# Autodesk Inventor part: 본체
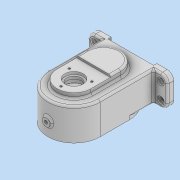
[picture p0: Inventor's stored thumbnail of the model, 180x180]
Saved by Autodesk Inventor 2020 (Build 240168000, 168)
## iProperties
Created: 2021-05
Part Number: 본체
Material: 일반
Document SubType Name: Modeling
Designer: Owner
Density: 1 g/cm^3
Appearance: 기본값
Mass: 280.11 g
Surface Area: 582.454 cm^2
Volume: 280.11 cm^3
Author: Owner
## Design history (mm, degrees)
sketch "스케치2"
  geometry: L1 (-61, 21.643)-(-35, 21.643); L2 (-35, 21.643)-(-35, -24.357); L3 (-35, -24.357)-(-61, -24.357); L4 (-61, -24.357)-(-61, 21.643); L5 (35, 21.643)-(61, 21.643); L6 (61, 21.643)-(61, -24.357); L7 (61, -24.357)-(35, -24.357); L8 (35, -24.357)-(35, 21.643); L9 (0, 30.578)-(0, 7.094); 1 further point
  constraints: 18 end point, 4 parallel, 2 horizontal, 2 perpendicular, 1 collinear, 1 point on line, 1 vertical, 2 other
  dimensions: "d2" = 46 distance of L1.end L2.end; "d3" = 46 distance of L7.end L5.start; "d4" = 122 distance between parallel lines of L6 L4; "d5" = 70 distance between parallel lines of L2 L8
extrude "돌출1" new body sketch "스케치2" distance "d6" = 10; taper "d7" = 0 deg
sketch "스케치3"
  geometry: L1 (-35, -92)-(-35, -47); L2 (5, -92)-(5, -47); L3 (-75, -47)-(-75, -92); L4 (-70, 0)-(-96, 0) reference; A1 r 40 centre (-35, -92) between (-75, -92) and (5, -92); A2 r 40 centre (-35, -47) between (5, -47) and (-75, -47); 2 further points
  constraints: 8 end point, 4 point on circle, 4 tangent, 2 centre point, 1 midpoint, 1 parallel, 1 vertical
  dimensions: "d8" = 80 distance between parallel lines of L2 L3; "d9" = 45 distance of L3.start L3.end; "d10" = 47 distance from line of L4 L3.start
extrude "돌출2" join sketch "스케치3" distance "d11" = 49; taper "d12" = 0 deg
sketch "스케치4"
  geometry: L1 (5, -92)-(5, -47) reference; L2 (5, -47)-(5, -10); L3 (0, -10)-(26, -10) reference; L4 (-75, -47)-(-75, -10); L5 (11.632, -5)-(-75, -5); L6 (26, 0)-(0, 0) reference; L7 (26, -10)-(0, -10) reference; L8 (0, 0)-(0, -10) reference; L9 (-70, 0)-(-70, -10) reference; L10 (-70, -10)-(-96, -10) reference; A1 r 40 centre (-35, -47) between (5, -47) and (-75, -47) reference; A2 r 40 centre (-35, -47) between (5, -47) and (-75, -47) reference; 3 further points
  constraints: 6 end point, 2 point on line, 2 vertical, 1 horizontal, 1 tangent
  dimensions: "d13" = 5 distance between parallel lines of L6 L5
extrude "돌출3" join sketch "스케치4" distance "d14" = 46; taper "d15" = 0 deg
sketch "스케치7"
  geometry: L1 (-35, 92)-(-35, 47); L2 (-65, 92)-(-65, 47); L3 (-5, 47)-(-5, 92); L4 (0, 0)-(26, 0) reference; A1 r 30 centre (-35, 92) between (-5, 92) and (-65, 92); A2 r 30 centre (-35, 47) between (-65, 47) and (-5, 47); 2 further points
  constraints: 8 end point, 4 point on circle, 4 tangent, 2 centre point, 1 midpoint, 1 parallel, 1 vertical, 1 vertical alignment
  dimensions: "d25" = 30 radius of A1; "d26" = 47 distance from line of L4 L1.end; "d27" = 45 distance of L1.end L1.start
extrude "돌출5" cut sketch "스케치7" distance "d28" = 41; taper "d29" = 0 deg
sketch "스케치8"
  geometry: L1 (61, -92)-(61, -47); L2 (87, -92)-(87, -47); L3 (35, -47)-(35, -92); L4 (122, 0)-(96, 0) reference; L5 (135.642, -62)-(-32.91, -62); A1 r 26 centre (61, -92) between (35, -92) and (87, -92); A2 r 26 centre (61, -47) between (87, -47) and (35, -47); 4 further points
  constraints: 10 end point, 4 point on circle, 4 tangent, 2 centre point, 1 horizontal, 1 midpoint, 1 parallel, 1 vertical, 1 vertical alignment
  dimensions: "d30" = 52 distance between parallel lines of L3 L2; "d31" = 47 distance from line of L4 L1.end; "d32" = 45 distance of L1.end L1.start; "d33" = 30 distance from line of L1.start L5
extrude "돌출6" join sketch "스케치8" distance "d34" = 8; taper "d35" = 0 deg
extrude "돌출7" join sketch "스케치8" distance "d36" = 11; taper "d37" = 0 deg
fillet "모깎기2" dims "d38" = 5
sketch "스케치10"
  geometry: L1 (26, 0)-(0, 0) reference; C1 r 14 at (61, -92); C2 r 11 at (61, -92); 1 further point
  constraints: 2 centre point, 1 coincident
  dimensions: "d46" = 28 diameter of C1; "d47" = 22 diameter of C2; "d48" = 92 distance from line of L1 C1.centre
extrude "돌출8" cut sketch "스케치10" distance "d49" = 4; taper "d50" = 0 deg
extrude "돌출9" cut sketch "스케치10" distance "d51" = 8; taper "d52" = 0 deg
sketch "스케치11"
  geometry: C1 r 14 at (0, 0); 1 further point
  constraints: 1 centre point
  dimensions: "d53" = 28 diameter of C1
extrude "돌출10" cut sketch "스케치11" extent not by distance; stored distance "d54" = 8; taper "d55" = 0 deg
sketch "스케치13"
  geometry: L1 (-55.627, 47)-(65.323, 47); L2 (-24.357, 0)-(21.643, 0) reference; L3 (13.643, 47)-(13.643, 92) reference; L4 (21.643, 61)-(21.643, 57); L5 (21.643, 57)-(25.643, 57); L6 (21.643, 47)-(32.643, 47) reference; L7 (21.643, 61)-(13.643, 61); L8 (25.643, 57)-(25.643, 47); 2 further points
  constraints: 10 end point, 2 horizontal, 2 point on line, 1 perpendicular, 1 vertical
  dimensions: "d59" = 47 distance between parallel lines of L2 L1; "d60" = 20 diameter of L5 L1; "d87" = 8 distance of L4.start L7.end; "d88" = 4 distance of L4.end L5.end
revolve "회전1" sketch "스케치13" stored, may be unused: angle "d63" = 90 deg
node "작업 평면1"
sketch "스케치14"
  geometry: L1 (-40, -27.357)-(40, -27.357) reference; C1 r 6 at (0, -6.357); 1 further point
  constraints: 1 centre point, 1 vertical alignment
  dimensions: "d66" = 21 distance from line of L1 C1.centre; "d67" = 12 diameter of C1
extrude "돌출11" join sketch "스케치14" stored distance "d68" = 8; taper "d69" = 0 deg
sketch "스케치15"
  geometry: 2 further points
hole "구멍1" sketch "스케치15" at (0, 0) diameter "d70" = 4.917; stored, may be unused: countersink angle "d74" = 90 deg, drill point angle "d76" = 118 deg; dims "d71" = 12, "d72" = 4, "d73" = 2, "d75" = 17.1
sketch "스케치16"
  geometry: L1 (-35, 92)-(-35, 47); L2 (0, 92)-(0, 47); L3 (-70, 47)-(-70, 92); L4 (0, 0)-(26, 0) reference; A1 r 35 centre (-35, 92) between (0, 92) and (-70, 92); A2 r 35 centre (-35, 47) between (-70, 47) and (0, 47); 8 further points
  constraints: 8 end point, 6 point on circle, 4 coincident, 4 tangent, 2 centre point, 1 midpoint, 1 parallel, 1 vertical
  dimensions: "d77" = 35 radius of A1; "d78" = 47 distance from line of L4 L1.end; "d79" = 45 distance of L1.end L1.start
hole "구멍2" sketch "스케치16" at (-70, 92), (-35, 127), (0, 92), (0, 47), (-35, 12), (-70, 47) diameter "d80" = 3.242; stored, may be unused: countersink angle "d84" = 90 deg, drill point angle "d86" = 118 deg; dims "d81" = 8, "d82" = 4, "d83" = 2, "d85" = 10
sketch "스케치17"
  geometry: L1 (-5, -49)-(75, -49) reference; 2 further points
  constraints: 1 vertical alignment
  dimensions: "d90" = 21 distance from line of L1 point (35, -28)
hole "구멍3" sketch "스케치17" at (35, -28) diameter "d91" = 4.917; stored, may be unused: countersink angle "d95" = 90 deg, drill point angle "d97" = 118 deg; dims "d92" = 12, "d93" = 12, "d94" = 1, "d96" = 17.1
sketch "스케치18"
  geometry: L1 (40, 21.643)-(40, -27.357) reference; L2 (10.022, -1.357)-(-26.327, -1.357); L3 (-35, -24.357)-(35, -24.357) reference; C1 r 5.5 at (51, -14.306); C2 r 5.5 at (51, 10.694); C3 r 3.3 at (51, -14.306); C4 r 3.3 at (51, 10.694); 1 further point
  constraints: 4 centre point, 2 coincident, 2 end point, 1 horizontal
  dimensions: "d117" = 11 diameter of C2; "d118" = 6.6 diameter of C4; "d119" = 11 diameter of C1; "d120" = 6.6 diameter of C3; "d123" = 11 distance from line of C1.centre L1; "d124" = 11 distance from line of L1 C2.centre; "d125" = 23 distance between parallel lines of L2 L3; "d128" = 25 distance of C2.centre C1.centre
fillet "모깎기5" dims "d98" = 3
fillet "모깎기6" dims "d99" = 3
fillet "모깎기7" dims "d100" = 3
sketch "스케치19"
  geometry: L1 (26, 0)-(0, 0) reference; A1 r 20 centre (61, -92) between (61, -112) and (43.679, -82); 2 further points
  constraints: 3 point on circle, 2 vertical alignment, 1 centre point
  dimensions: "d101" = 92 distance from line of A1.centre L1; "d102" = 40 diameter of A1; "d103" = 120 deg dimension on A1.centre A1.end A1.start; "d104" = 120 deg dimension on A1.centre point (78.321, -82) A1.start
hole "구멍4" sketch "스케치19" at (43.679, -82), (61, -112), (78.321, -82) diameter "d105" = 3.242; stored, may be unused: countersink angle "d109" = 90 deg, drill point angle "d111" = 118 deg; dims "d106" = 8, "d107" = 4, "d108" = 2, "d110" = 10
fillet "모깎기8" dims "d112" = 0.3
fillet "모깎기9" dims "d113" = 3
chamfer "모따기1" distance "d114" = 1; stored, may be unused: second distance "d115" = 2, angle "d116" = 45 deg
fillet "모깎기11" dims "d122" = 10
extrude "돌출12" cut sketch "스케치18" distance "d129" = 2; taper "d130" = 0 deg
extrude "돌출13" cut sketch "스케치18" extent not by distance; stored distance "d131" = 0; taper "d132" = 0 deg
fillet "모깎기12" dims "d133" = 3
node "솔리드1"
mirror "미러1"
feature "A9D066F2-1C7D-4E18-AEED-F7BC21143FA4" dims "d80" = 3.242, "d81" = 8, "d82" = 4, "d83" = 2, "d84" = 90 deg, "d85" = 10, "d86" = 118 deg
other parameters: "d65" = -135
